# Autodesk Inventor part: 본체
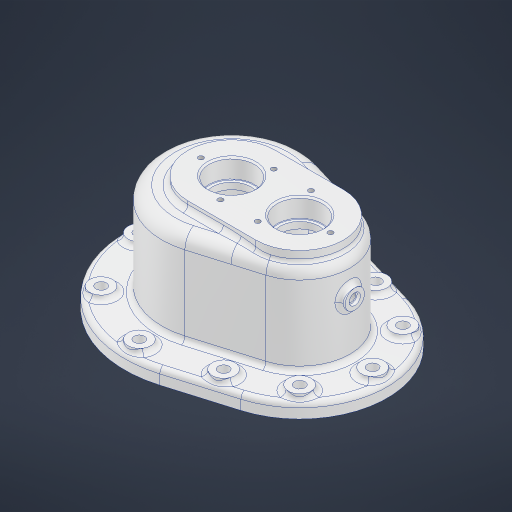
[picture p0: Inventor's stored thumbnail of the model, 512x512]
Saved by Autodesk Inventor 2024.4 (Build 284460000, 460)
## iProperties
Created: 2026-03
Part Number: 본체
Material: 알루미늄 6061
Document SubType Name: Modeling
Designer: user
Density: 2.7 g/cm^3
Appearance: 알루미늄 - 평지
Mass: 770.437 g
Surface Area: 813.797 cm^2
Volume: 285.347 cm^3
Author: user
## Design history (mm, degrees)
sketch "스케치1"
  geometry: L1 (0, 0)-(-42, 0); L2 (1.56, 69.336)-(-79.766, 45.089); L3 (-0.924, -68.595)-(-85.409, -43.407); C1 r 66 at (0, 0); C2 r 54 at (-42, 0); 5 further points
  constraints: 6 end point, 4 tangent, 2 centre point, 2 coincident, 1 horizontal
  dimensions: "d0" = 132 diameter of C1; "d1" = 42 distance of L1.start L1.end; "d2" = 108 diameter of C2
extrude "돌출1" new body sketch "스케치1" distance "d3" = 9; taper "d4" = 0 deg
sketch "스케치2"
  geometry: L1 (7.218, -42.718)-(66.311, -25.1); L2 (63.565, 25.919)-(1.425, 44.446); C1 r 43 at (0, 0); C2 r 31 at (42, 0); A1 r 54 centre (42, 0) between (57.429, -51.749) and (57.429, 51.749) reference; A2 r 66 centre (0, 0) between (18.857, 63.249) and (18.857, -63.249) reference; 4 further points
  constraints: 4 end point, 4 tangent, 2 centre point, 2 coincident
  dimensions: "d5" = 86 diameter of C1; "d6" = 62 diameter of C2
extrude "돌출2" join sketch "스케치2" distance "d7" = 57; taper "d8" = 0 deg
sketch "스케치3"
  geometry: L1 (0, -27)-(42, -27); L2 (42, 27)-(0, 27); A1 r 31 centre (42, 0) between (50.857, -29.708) and (50.857, 29.708) reference; A2 r 43 centre (0, 0) between (12.286, 41.208) and (12.286, -41.208) reference; A3 r 27 centre (0, 0) between (0, -27) and (0, 27); A4 r 27 centre (42, 0) between (42, -27) and (42, 27)
  constraints: 4 end point, 4 point on circle, 2 centre point, 2 coincident, 1 horizontal, 1 parallel, 1 tangent
  dimensions: "d9" = 54 diameter of A3; "d10" = 54 diameter of A4
extrude "돌출3" join sketch "스케치3" distance "d11" = 5; taper "d12" = 0 deg
sketch "스케치4"
  geometry: C1 r 19 at (0, 0); C2 r 19 at (42, 0); A1 r 27 centre (42, 0) between (42, -27) and (42, 27) reference; A2 r 27 centre (0, 0) between (0, 27) and (0, -27) reference; 2 further points
  constraints: 4 coincident, 2 centre point
  dimensions: "d13" = 38 diameter of C1; "d14" = 38 diameter of C2
hole "구멍1" sketch "스케치4" at (0, 0), (42, 0) diameter "d15" = 24; stored, may be unused: countersink angle "d19" = 90 deg, drill point angle "d21" = 0 deg; dims "d16" = 9, "d17" = 28, "d18" = 12, "d20" = 16
sketch "스케치5"
  geometry: L1 (-29.714, -41.208)-(8.857, -29.708) reference; L2 (8.857, 29.708)-(-29.714, 41.208) reference; L3 (-31.143, 36.416)-(7.429, 24.916); L4 (7.429, -24.916)-(-31.143, -36.416); C1 r 12 at (0, 0) reference; A1 r 43 centre (-42, 0) between (-29.714, 41.208) and (-29.714, -41.208) reference; A2 r 31 centre (0, 0) between (8.857, -29.708) and (8.857, 29.708) reference; A3 r 38 centre (-42, 0) between (-31.143, 36.416) and (-31.143, -36.416); A4 r 26 centre (0, 0) between (7.429, -24.916) and (7.429, 24.916); 1 further point
  constraints: 4 end point, 4 point on circle, 2 centre point, 3 other
  dimensions: "d22" = 5 radial gap between concentric circles of A1 A3
extrude "돌출4" cut sketch "스케치5" distance "d23" = 37; taper "d24" = 0 deg
sketch "스케치6"
  geometry: L1 (-31.143, 36.416)-(7.429, 24.916) reference; L2 (7.429, -24.916)-(-31.143, -36.416) reference; L3 (-42, 0)-(-80, 0); L4 (-18.073, 8.125)-(-90.791, 50.109); L5 (-9.415, -3.126)-(-97.468, -53.964); L6 (-72.678, -48.799)-(42.051, -14.594); L7 (58.931, 9.561)-(-31.143, 36.416); L8 (-31.143, 36.416)-(-58.069, 44.444); C1 r 19 at (-42, 0); A1 r 38 centre (-42, 0) between (-31.143, 36.416) and (-31.143, -36.416) reference; A2 r 26 centre (0, 0) between (7.429, -24.916) and (7.429, 24.916) reference; A3 r 26 centre (0, 0) between (-11.857, 23.139) and (7.429, -24.916); A4 r 38 centre (-42, 0) between (-31.143, 36.416) and (-31.143, -36.416); A5 r 38 centre (-42, 0) between (-11.857, 23.139) and (-31.143, 36.416); A6 r 26 centre (0, 0) between (7.429, 24.916) and (-11.857, 23.139); A7 r 26 centre (0, 0) between (7.429, -24.916) and (7.429, 24.916); A8 r 38 centre (-42, 0) between (-31.143, -36.416) and (-11.857, 23.139); 4 further points
  constraints: 13 end point, 13 point on circle, 13 tangent, 7 centre point, 3 coincident, 2 concentric, 2 point on line
  dimensions: "d25" = 38 diameter of C1; "d28" = 30 deg angle of L3 L4; "d29" = 60 deg angle of L5 L4
extrude "돌출5" cut sketch "스케치6" extent not by distance; stored distance "d30" = 0; taper "d31" = 0 deg
sketch "스케치7"
  geometry: L1 (57.429, 51.749)-(18.857, 63.249) reference; L2 (18.857, -63.249)-(57.429, -51.749) reference; L3 (0, 0)-(0, -57); L4 (0, 0)-(0, 57); L5 (0, 0)-(-63.062, 63.062); L6 (0, 0)-(-73.974, -73.974); L7 (18.857, -63.249)-(57.429, -51.749) reference; L8 (57.429, 51.749)-(18.857, 63.249) reference; L9 (16.286, -54.624)-(54.857, -43.124); L10 (54.857, 43.124)-(16.286, 54.624); L11 (0, 0)-(42, 0); L12 (42, 0)-(42, -67.903); L13 (42, -67.903)-(42, 86.484); L14 (42, 0)-(119.528, 0); L15 (42, 0)-(99.754, -57.754); L16 (42, 0)-(112.262, 70.262); L17 (0, 0)-(-57, 0); C1 r 12 at (0, 0) reference; C2 r 7 at (-57, 0); C3 r 7 at (-40.305, 40.305); C4 r 7 at (-40.305, -40.305); C5 r 7 at (0, 57); C6 r 7 at (0, -57); C7 r 7 at (42, -46.957); C8 r 7 at (42, 46.957); C9 r 7 at (73.82, 31.82); C10 r 7 at (87, 0); C11 r 7 at (73.82, -31.82); A1 r 54 centre (42, 0) between (57.429, -51.749) and (57.429, 51.749) reference; A2 r 45 centre (42, 0) between (87, 0) and (73.82, 31.82); A3 r 57 centre (0, 0) between (0, -57) and (0, 57); 5 further points
  constraints: 26 end point, 12 centre point, 10 coincident, 9 point on line, 8 point on circle, 3 horizontal, 2 parallel, 2 vertical
  dimensions: "d32" = 90 diameter of A2; "d33" = 114 diameter of A3; "d34" = 45 deg angle of L6 L3; "d35" = 45 deg angle of L4 L5; "d36" = 14 diameter of C2; "d37" = 14 diameter of C3; "d38" = 14 diameter of C4; "d39" = 14 diameter of C5; "d40" = 14 diameter of C6; "d41" = 9 distance between parallel lines of L2 L9; "d42" = 9 distance between parallel lines of L1 L10; "d43" = 42 distance of L11.start L11.end; "d44" = 45 deg angle of L14 L16; "d45" = 45 deg angle of L15 L14; "d46" = 14 diameter of C7; "d47" = 14 diameter of C8; "d48" = 14 diameter of C9; "d49" = 14 diameter of C10; "d50" = 14 diameter of C11; "d51" = 42 horizontal distance of point (42, -46.957) C6.centre
extrude "돌출6" join sketch "스케치7" distance "d52" = 3; taper "d53" = 0 deg
sketch "스케치8"
  geometry: C1 r 7 at (0, 0) reference; C2 r 7 at (-82.305, 6.652) reference; C3 r 7 at (-99, 46.957) reference; C4 r 7 at (-82.305, 87.263) reference; C5 r 7 at (-42, 103.957) reference; C6 r 7 at (0, 93.915) reference; C7 r 7 at (31.82, 78.777) reference; C8 r 7 at (45, 46.957) reference; C9 r 7 at (31.82, 15.138) reference; C10 r 7 at (-42, -10.043) reference; 11 further points
  constraints: 10 coincident
hole "구멍2" sketch "스케치8" at (-82.305, 6.652), (-99, 46.957), (-82.305, 87.263), (-42, 103.957), (0, 93.915), (31.82, 78.777), (45, 46.957), (31.82, 15.138), (0, 0), (-42, -10.043) diameter "d54" = 6.6; stored, may be unused: countersink angle "d58" = 90 deg, drill point angle "d60" = 0 deg; dims "d55" = 6, "d56" = 4, "d57" = 2, "d59" = 8
fillet "모깎기1" dims "d61" = 0.3
chamfer "모따기1" distance "d62" = 1; stored, may be unused: second distance "d63" = 2, angle "d64" = 45 deg
sketch "스케치9" dims "d65" = 38
  geometry: C1 r 15 at (0, 0) reference; C2 r 19 at (42, 0); A1 r 27 centre (42, 0) between (42, -27) and (42, 27) reference; 2 further points
  constraints: 2 coincident, 1 centre point, 1 horizontal alignment, 2 other
  dimensions: "d66" = 38 diameter of C2
hole "구멍3" sketch "스케치9" at (-19, 0) diameter "d67" = 3.242; stored, may be unused: countersink angle "d71" = 90 deg, drill point angle "d73" = 118 deg; dims "d68" = 8, "d69" = 4, "d70" = 2, "d72" = 10
sketch "스케치10" dims "d77" = 38
  geometry: A1 r 27 centre (42, 0) between (42, -27) and (42, 27) reference; 2 further points
  constraints: 1 coincident, 1 horizontal alignment, 2 other
hole "구멍4" sketch "스케치10" at (61, 0) diameter "d78" = 3.242; stored, may be unused: countersink angle "d82" = 90 deg, drill point angle "d84" = 118 deg; dims "d79" = 8, "d80" = 4, "d81" = 2, "d83" = 10
node "작업 평면1"
sketch "스케치11"
  geometry: L1 (0, 0)-(43, 0); C1 r 6 at (43, 0)
  constraints: 2 end point, 1 centre point, 1 coincident, 1 horizontal
  dimensions: "d89" = 43 distance of L1.start L1.end; "d90" = 12 diameter of C1
extrude "돌출7" join sketch "스케치11" stored distance "d91" = 3; taper "d92" = 0 deg
node "작업 평면2"
sketch "스케치12"
  geometry: L1 (0, 0)-(43, 0); C1 r 6 at (43, 0)
  constraints: 2 end point, 1 centre point, 1 coincident, 1 horizontal
  dimensions: "d94" = 43 distance of L1.start L1.end; "d95" = 12 diameter of C1
extrude "돌출8" join sketch "스케치12" stored distance "d96" = 10; taper "d97" = 0 deg
sketch "스케치13"
  geometry: C1 r 6 at (0, 0) reference; C2 r 3.5 at (0, 0); 2 further points
  constraints: 2 coincident, 1 centre point
  dimensions: "d98" = 7 diameter of C2
extrude "돌출9" cut sketch "스케치13" distance "d99" = 2; taper "d100" = 0 deg
sketch "스케치14"
  geometry: C1 r 6 at (0, 0) reference; C2 r 3.5 at (0, 0); 1 further point
  constraints: 1 centre point, 1 coincident
  dimensions: "d101" = 7 diameter of C2
extrude "돌출10" cut sketch "스케치14" distance "d102" = 2; taper "d103" = 0 deg
sketch "스케치15"
  geometry: C1 r 3.5 at (0, 0) reference; 2 further points
  constraints: 1 coincident
hole "구멍5" sketch "스케치15" at (0, 0) diameter "d104" = 5.1881; stored, may be unused: countersink angle "d108" = 90 deg, drill point angle "d110" = 118 deg; dims "d105" = 12, "d106" = 4, "d107" = 2, "d109" = 16
sketch "스케치16"
  geometry: C1 r 3.5 at (0, 0) reference; 2 further points
  constraints: 1 coincident
hole "구멍6" sketch "스케치16" at (0, 0) diameter "d111" = 5.1881; stored, may be unused: countersink angle "d115" = 90 deg, drill point angle "d117" = 118 deg; dims "d112" = 12, "d113" = 4, "d114" = 2, "d116" = 16
fillet "모깎기2" dims "d118" = 8
fillet "모깎기3" dims "d119" = 3
fillet "모깎기4" dims "d120" = 3
fillet "모깎기5" dims "d121" = 3
fillet "모깎기6" dims "d122" = 3
fillet "모깎기7" dims "d123" = 3
sketch "스케치17"
  geometry: C1 r 14 at (0, 0); A1 r 35 centre (0, 0) between (10, 33.541) and (10, -33.541) reference
  constraints: 1 centre point, 1 coincident
  dimensions: "d124" = 28 diameter of C1
extrude "돌출11" cut sketch "스케치17" distance "d125" = 3.65; taper "d126" = 0 deg
sketch "스케치18"
  geometry: C1 r 14 at (0, 0) reference; 1 further point
  constraints: 1 coincident
hole "구멍7" sketch "스케치18" at (0, 0) diameter "d127" = 28; stored, may be unused: countersink angle "d131" = 90 deg, drill point angle "d133" = 0 deg; dims "d128" = 12, "d129" = 29.4, "d130" = 1.35, "d132" = 9.35
sketch "스케치19"
  geometry: C1 r 14 at (0, 0) reference; C2 r 12 at (0, 0)
  constraints: 1 centre point, 1 coincident
  dimensions: "d134" = 24 diameter of C2
extrude "돌출12" cut sketch "스케치19" distance "d135" = 20; taper "d136" = 0 deg
fillet "모깎기8" dims "d137" = 0.3
chamfer "모따기2" distance "d138" = 1; stored, may be unused: second distance "d139" = 2, angle "d140" = 45 deg
sketch "스케치21"
  geometry: 1 further point
sketch "스케치23" dims "d0" = 132, "d1" = 42, "d2" = 108
  geometry: L1 (66, 0)-(-66, 0) reference; 6 further points
  constraints: 2 midpoint, 1 vertical alignment, 1 other
  dimensions: "d144" = 25 distance of point (0, 25) point (0, 0)
feature "엠보싱2" sketch "스케치23" dims "d145" = 0.5, "d146" = 0
node "솔리드1"
pattern_circular "원형 패턴1" dims angle "d75" = 360 deg
pattern_circular "원형 패턴2" dims angle "d86" = 360 deg
feature "A9D066F2-1C7D-4E18-AEED-F7BC21143FA4" dims "d15" = 24, "d16" = 9, "d17" = 28, "d18" = 12, "d19" = 90 deg, "d20" = 16, "d21" = 0
other parameters: "d88" = -46, "d93" = 76
